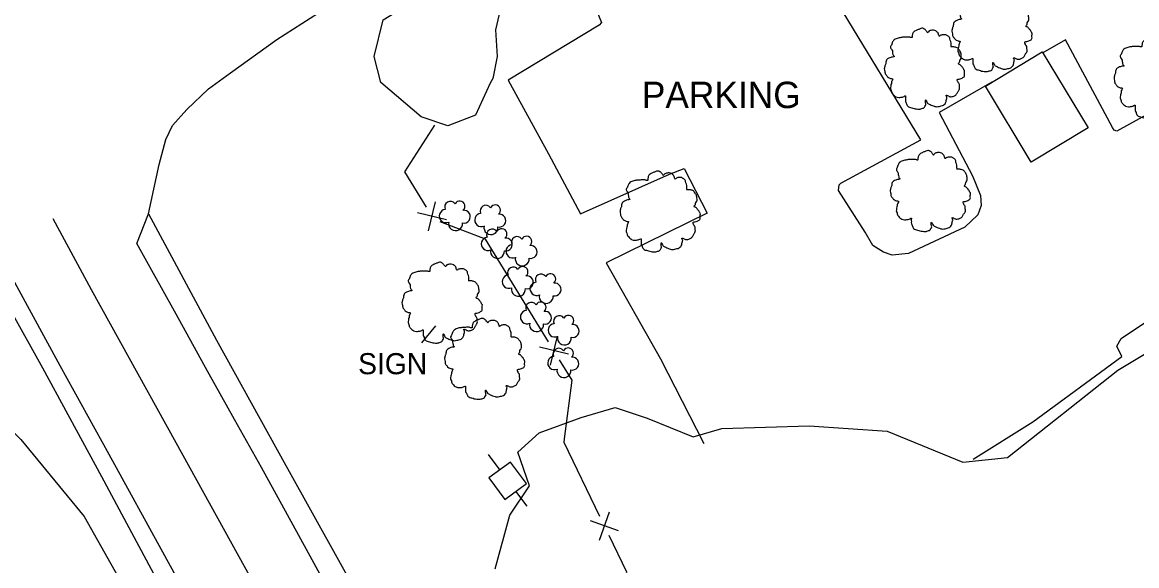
# Model space of a CAD drawing. Extents: x 2160437 to 2172832, y 205694 to 212444.
# Drawn here: x 2171800.7 to 2172011.7, y 206184.5 to 206287.5 of the extents above; entities that cross this region are included whole.
import ezdxf

# ---------------------------------------------------------------- set-up
doc = ezdxf.new("R2010")
doc.units = 0
for name, color, linetype in [('Default', 7, 'Continuous'), ('RD_EX_Bldg', 7, 'Continuous'), ('RD_EX_Bldg_Signs', 7, 'Continuous'), ('RD_EX_BldgApp_txCode', 7, 'Continuous'), ('RD_EX_Fence_Other', 7, 'Continuous'), ('RD_EX_LaneStripe', 7, 'Continuous'), ('RD_EX_Parking_Paved', 7, 'Continuous'), ('RD_EX_Road', 7, 'Continuous'), ('RD_EX_Road_txCode', 7, 'Continuous'), ('RD_EX_UT', 7, 'Continuous'), ('RD_EX_VEG', 7, 'Continuous'), ('RD_EX_VEG_TreeLine', 7, 'Continuous')]:
    doc.layers.add(name, color=color, linetype=linetype)

# ---------------------------------------------------------------- blocks, each defined once
blk = doc.blocks.new('RD_EX_Fnce_Other')
at = {"layer": 'Default'}
for points in [[(-0.0417, -0.0417), (0.0417, 0.0417)], [(-0.0417, 0.0417), (0.0417, -0.0417)]]:
    blk.add_lwpolyline(points, dxfattribs=at)
blk = doc.blocks.new('T2')
at = {"layer": 'RD_EX_VEG'}
for points in [[(0.05, 7.21), (-0.25, 7.24), (-0.57, 7.14), (-0.82, 7.04), (-1.05, 6.96), (-1.27, 6.86), (-1.57, 6.69), (-1.8, 6.49), (-1.92, 6.24), (-1.97, 6.01), (-2.02, 5.74), (-2.02, 5.56), (-2.15, 5.54), (-2.3, 5.56), (-2.55, 5.64), (-2.8, 5.64), (-3.05, 5.64), (-3.4, 5.61), (-3.75, 5.61), (-4.02, 5.56), (-4.35, 5.51), (-4.72, 5.39), (-5.07, 5.26), (-5.37, 5.01), (-5.62, 4.54), (-5.75, 4.19), (-5.9, 3.94), (-5.75, 3.49), (-5.57, 3.14), (-5.55, 2.94), (-5.47, 2.52), (-5.37, 2.29), (-5.25, 2.09), (-5.32, 2.07), (-5.7, 2.02), (-6, 1.92), (-6.42, 1.69), (-6.64, 1.47), (-6.74, 1.14), (-6.77, 0.79), (-6.87, 0.59), (-6.94, 0.32), (-6.97, 0.24), (-7.02, -0.08), (-6.92, -0.53), (-6.89, -0.88), (-6.77, -1.11), (-6.62, -1.28), (-6.44, -1.53), (-6.05, -1.76), (-5.72, -1.86), (-5.52, -1.88), (-5.7, -2.38), (-5.75, -2.73), (-5.87, -3.13), (-5.87, -3.21), (-5.92, -3.68), (-5.77, -4.01), (-5.7, -4.38), (-5.52, -4.61), (-5.25, -4.91), (-4.92, -5.13), (-4.42, -5.26), (-4.02, -5.23), (-3.45, -5.06), (-3.2, -4.98), (-3.22, -5.16), (-3.2, -5.53), (-3.2, -5.96), (-3.05, -6.28), (-2.95, -6.56), (-2.8, -6.81), (-2.47, -7.03), (-2.07, -7.11), (-1.65, -7.26), (-1.2, -7.33), (-0.7, -7.36), (-0.1, -7.21), (0.18, -7.08), (0.28, -6.91), (0.48, -6.53), (0.43, -6.31), (0.45, -5.71), (0.55, -5.88), (0.73, -6.23), (1.23, -6.53), (1.63, -6.71), (2.1, -6.86), (2.4, -6.93), (2.88, -6.86), (3.25, -6.78), (3.63, -6.66), (3.93, -6.38), (4.1, -6.11), (4.15, -5.83), (4.23, -5.46), (4.28, -5.28)], [(4.28, -5.28), (4.2, -5.11), (4.15, -4.86), (4.23, -4.88), (4.4, -4.93), (4.68, -5.06), (4.9, -5.13), (5.23, -5.11), (5.5, -5.01), (5.95, -4.73), (6.22, -4.26), (6.5, -3.86), (6.57, -3.53), (6.52, -3.31), (6.5, -2.81), (6.3, -2.56), (6.25, -2.43), (6.15, -2.03), (6.22, -1.98), (6.5, -1.93), (6.87, -1.81), (7.15, -1.68), (7.37, -1.51), (7.45, -1.28), (7.42, -0.88), (7.47, -0.48), (7.4, -0.33), (7.3, -0.18), (7.22, 0.02), (7.07, 0.17), (6.97, 0.32), (6.87, 0.42), (6.75, 0.57), (6.57, 0.69), (6.42, 0.74), (6.37, 0.89), (6.52, 1.09), (6.57, 1.19), (6.6, 1.42), (6.82, 1.77), (6.87, 2.17), (6.82, 2.59), (6.77, 2.87), (6.62, 3.14), (6.42, 3.39), (6.3, 3.56), (6.12, 3.69), (5.8, 3.81), (5.55, 3.86), (5.2, 3.86), (5, 3.91), (5.03, 3.96), (5.03, 4.11), (5.03, 4.39), (4.95, 4.84), (4.8, 5.34), (4.8, 5.36), (4.7, 5.61), (4.48, 5.81), (4.3, 5.91), (4.1, 6.04), (3.85, 6.06), (3.55, 6.06), (3.28, 6.01), (3.08, 5.91), (2.9, 5.79), (2.83, 5.94), (2.73, 6.24), (2.68, 6.39), (2.53, 6.56), (2.3, 6.76), (1.85, 6.89), (1.23, 6.81), (0.93, 6.61), (0.78, 6.44), (0.73, 6.56), (0.53, 6.76), (0.43, 6.94), (0.25, 7.06), (0.1, 7.16), (0, 7.21)]]:
    blk.add_spline(points, degree=3, dxfattribs=at)
blk = doc.blocks.new('PP')
at = {"layer": 'RD_EX_UT'}
for p, q in [((2.49, 2.51), (-2.51, 2.51)), ((-2.51, 2.51), (-2.51, -2.49)), ((2.49, -2.49), (2.49, 2.51)), ((-5.94, -0.05), (-2.47, -0.05)), ((2.42, -0.05), (6.06, -0.05)), ((-2.51, -2.49), (2.49, -2.49))]:
    blk.add_line(p, q, dxfattribs=at)

msp = doc.modelspace()

# ---------------------------------------------------------------- linework, layer by layer
at = {"layer": 'RD_EX_Bldg'}
msp.add_lwpolyline([(2171993.84, 206281.88), (2172002.51, 206267.47), (2171991.72, 206260.98), (2171983.06, 206275.39)], close=True, dxfattribs=at)
at = {"layer": 'RD_EX_Bldg_Signs'}
msp.add_lwpolyline([(2171878.9, 206229.93), (2171876.26, 206226.72)], dxfattribs=at)
at = {"layer": 'RD_EX_Fence_Other'}
for points in [[(2171877.21, 206252.42), (2171873.1, 206259.12), (2171878.81, 206268)], [(2171900.33, 206226.91), (2171888.41, 206246.36), (2171879.83, 206249.65)], [(2171910.06, 206193.82), (2171903.27, 206207.82), (2171903.35, 206208.53), (2171904.8, 206219.64), (2171902.43, 206223.5)], [(2171917.26, 206161.07), (2171911.5, 206171.27), (2171915.18, 206183.25), (2171911.8, 206190.22)]]:
    msp.add_lwpolyline(points, dxfattribs=at)
at = {"layer": 'RD_EX_LaneStripe'}
msp.add_lwpolyline([(2171915.41, 206052.28), (2171908.6, 206064.84), (2171894.59, 206090.36), (2171876.39, 206123.47), (2171863.18, 206147.44), (2171846.75, 206177.09), (2171829.84, 206207.77), (2171813.79, 206236.79), (2171806.5, 206250.2)], dxfattribs=at)
at = {"layer": 'RD_EX_Parking_Paved'}
for points in [[(2171887.33, 206307.57), (2171892.53, 206306.58), (2171896.05, 206305.57), (2171898.96, 206304.53), (2171901.25, 206303.4), (2171904.57, 206298.7), (2171909.15, 206290.36), (2171910.34, 206287.47), (2171909.9, 206286.91), (2171892.71, 206276.54), (2171900.34, 206262.54), (2171906.36, 206251.17), (2171923.25, 206258.68), (2171926.03, 206259.79), (2171930.39, 206251.32), (2171911.27, 206241.91), (2171921.51, 206223.68), (2171929.73, 206207.64)], [(2171984.28, 206276.13), (2171974.29, 206270.4), (2171980.64, 206258.36), (2171982.14, 206254.64), (2171982.29, 206252.75), (2171981.64, 206250.98), (2171979.17, 206248.66), (2171968.5, 206243.66), (2171965.38, 206243.36), (2171963.75, 206243.89), (2171961.77, 206245.2), (2171960.28, 206247.7), (2171955.23, 206255.61), (2171955.35, 206256.66), (2171955.71, 206257.01), (2171970.86, 206265.23), (2171955.26, 206290.84)], [(2171980.74, 206204.65), (2171992.05, 206211.74), (2172008.92, 206224.14), (2172007.94, 206226.1), (2172008.79, 206227.54), (2172017.45, 206233.35), (2172013.54, 206244.08), (2172019.01, 206247.66), (2172018.01, 206249.68), (2172018.37, 206251.59), (2172019.95, 206252.84), (2172021.51, 206252.84), (2172024.02, 206255.34), (2172026.11, 206255.5), (2172030.82, 206258.52), (2172029.45, 206260.96), (2172027.87, 206261.93), (2172026.71, 206263.93), (2172021.33, 206274.21), (2172007.96, 206266.84), (2172007.44, 206267.03), (2172007.16, 206267.51), (2171998.23, 206284.13), (2171993.96, 206281.68)]]:
    msp.add_lwpolyline(points, dxfattribs=at)
at = {"layer": 'RD_EX_Road'}
for points in [[(2171901.39, 206044.47), (2171876.6, 206089.89), (2171865.46, 206109.54), (2171853.29, 206132.68), (2171840.93, 206155.1), (2171828.92, 206176.69), (2171815.72, 206201.3), (2171804.53, 206221.91), (2171792.02, 206244.4), (2171781.36, 206262.89), (2171770.61, 206282.85), (2171757.79, 206306.7), (2171746.12, 206327.48), (2171731.4, 206354.36), (2171711.51, 206390.94), (2171700.93, 206410.28), (2171689.86, 206429.77), (2171676.21, 206454.51)], [(2171836.45, 206170.39), (2171827.66, 206186.35), (2171817.1, 206205.56), (2171807.83, 206222.34), (2171799.68, 206237.32), (2171792.13, 206251.21), (2171784.29, 206265.31), (2171777.35, 206278.32), (2171770.46, 206291), (2171763.06, 206304.69), (2171755.78, 206317.77), (2171749.27, 206329.78), (2171743.28, 206340.99), (2171736.95, 206352.74), (2171729.52, 206366.17), (2171723.11, 206377.94), (2171717.71, 206387.79), (2171710.52, 206400.59), (2171703.76, 206412.95), (2171697.2, 206424.8), (2171689.07, 206439.41), (2171682.16, 206452.06)], [(2171861.37, 206174.9), (2171855.54, 206185.56), (2171850.89, 206194.12), (2171845.97, 206203.06), (2171840.88, 206212.21), (2171835.73, 206221.38), (2171829.78, 206232.17), (2171824.6, 206241.56), (2171822.35, 206245.55), (2171824.57, 206251.19), (2171826.57, 206260.55), (2171827.86, 206265.24), (2171829.11, 206267.91), (2171831.84, 206270.92), (2171835.93, 206274.88), (2171840.11, 206277.88), (2171848.89, 206284.2), (2171856.74, 206289.3)], [(2171824.57, 206251.19), (2171837.47, 206227.23), (2171850.56, 206203.48), (2171865.85, 206176.01), (2171872.19, 206163.72), (2171883.23, 206144.6), (2171897.67, 206117.65), (2171913.38, 206089.35), (2171928.64, 206061.43)]]:
    msp.add_lwpolyline(points, dxfattribs=at)
at = {"layer": 'RD_EX_VEG'}
for centre, radius, start, end in [((2171881.74, 206252.46), 1.08, 34.9763, 204.756), ((2171883.51, 206252.61), 0.995, 308.7626, 152.0467), ((2171888.45, 206251.72), 1.08, 34.9763, 204.756), ((2171890.22, 206251.87), 0.995, 308.7626, 152.0467), ((2171880.9, 206250.75), 1.26, 96.4518, 294.734), ((2171884.3, 206250.63), 1.22, 256.5667, 98.1046), ((2171887.61, 206250.01), 1.26, 96.4518, 294.734), ((2171891.01, 206249.89), 1.22, 256.5667, 98.1046), ((2171882.71, 206249.31), 1.32, 166.8827, 5.7589), ((2171889.42, 206248.57), 1.32, 166.8827, 5.7589), ((2171889.69, 206247.2), 1.08, 34.9763, 204.756), ((2171891.46, 206247.35), 0.995, 308.7626, 152.0467), ((2171888.85, 206245.49), 1.26, 96.4518, 294.734), ((2171892.25, 206245.37), 1.22, 256.5667, 98.1046), ((2171894.38, 206245.78), 1.08, 34.9763, 204.756), ((2171896.15, 206245.93), 0.995, 308.7626, 152.0467), ((2171890.66, 206244.05), 1.32, 166.8827, 5.7589), ((2171893.54, 206244.07), 1.26, 96.4518, 294.734), ((2171896.94, 206243.95), 1.22, 256.5667, 98.1046), ((2171895.35, 206242.63), 1.32, 166.8827, 5.7589), ((2171893.66, 206240.02), 1.08, 34.9763, 204.756), ((2171895.43, 206240.17), 0.995, 308.7626, 152.0467), ((2171900.69, 206238.82), 0.995, 308.7626, 152.0467), ((2171892.82, 206238.31), 1.26, 96.4518, 294.734), ((2171896.22, 206238.19), 1.22, 256.5667, 98.1046), ((2171898.08, 206236.96), 1.26, 96.4518, 294.734), ((2171898.92, 206238.67), 1.08, 34.9763, 204.756), ((2171901.48, 206236.84), 1.22, 256.5667, 98.1046), ((2171894.63, 206236.87), 1.32, 166.8827, 5.7589), ((2171899.89, 206235.52), 1.32, 166.8827, 5.7589), ((2171897.09, 206233.31), 1.08, 34.9763, 204.756), ((2171898.86, 206233.46), 0.995, 308.7626, 152.0467), ((2171896.25, 206231.6), 1.26, 96.4518, 294.734), ((2171899.65, 206231.48), 1.22, 256.5667, 98.1046), ((2171902.35, 206230.79), 1.08, 34.9763, 204.756), ((2171904.12, 206230.94), 0.995, 308.7626, 152.0467), ((2171898.06, 206230.16), 1.32, 166.8827, 5.7589), ((2171901.51, 206229.08), 1.26, 96.4518, 294.734), ((2171904.91, 206228.96), 1.22, 256.5667, 98.1046), ((2171903.32, 206227.64), 1.32, 166.8827, 5.7589), ((2171902.28, 206224.61), 1.08, 34.9763, 204.756), ((2171904.05, 206224.76), 0.995, 308.7626, 152.0467), ((2171901.44, 206222.9), 1.26, 96.4518, 294.734), ((2171904.84, 206222.78), 1.22, 256.5667, 98.1046), ((2171903.25, 206221.46), 1.32, 166.8827, 5.7589)]:
    msp.add_arc(centre, radius, start, end, dxfattribs=at)
at = {"layer": 'RD_EX_VEG_TreeLine'}
for points in [[(2171889.3, 206275.92), (2171886.47, 206269.85), (2171881.27, 206267.85), (2171876.18, 206269.56), (2171868.58, 206276.05), (2171867.34, 206281.02), (2171869.03, 206287.94), (2171874.4, 206291.25), (2171877.74, 206298.05), (2171883.4, 206300.36), (2171889.64, 206298.13), (2171891.67, 206292.07), (2171890.3, 206286.07), (2171890.63, 206281), (2171889.77, 206276.8)], [(2171800.41, 206208.4), (2171812.38, 206193.79), (2171822.52, 206175.87), (2171820.25, 206163.95), (2171812.17, 206169.17), (2171801.14, 206179.59), (2171789.35, 206199.34), (2171788.93, 206210.22), (2171794.15, 206212.74), (2171797.31, 206211.71), (2171798.85, 206209.94)]]:
    msp.add_lwpolyline(points, close=True, dxfattribs=at)
msp.add_lwpolyline([(2171890.22, 206183.89), (2171892.98, 206194.06), (2171896.71, 206199.62), (2171894.5, 206205.98), (2171898.55, 206209.67), (2171906.5, 206212.54), (2171912.96, 206214.49), (2171918.98, 206212.47), (2171927.74, 206208.9), (2171933.13, 206210.48), (2171949.69, 206211), (2171964.49, 206210), (2171978.79, 206204.13), (2171987.22, 206204.96), (2172008.12, 206221.53), (2172021.21, 206229.35)], dxfattribs=at)

# ---------------------------------------------------------------- block references
at = {"layer": 'RD_EX_Fence_Other'}
for p, xscale, yscale, rotation in [((2171878.26, 206250.72), 48, 48, 121.52972699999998), ((2171901.38, 206225.21), 48, 48, 121.52413500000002), ((2171910.93, 206192.02), 47.99999999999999, 48.00000000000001, 115.841673)]:
    msp.add_blockref('RD_EX_Fnce_Other', p, dxfattribs=dict(at, xscale=xscale, yscale=yscale, rotation=rotation))
at = {"layer": 'RD_EX_UT', "xscale": 1.0199999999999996, "yscale": 1.02, "rotation": 126.43732600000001}
msp.add_blockref('PP', (2171892.62, 206200.58), dxfattribs=at)
at = {"layer": 'RD_EX_VEG', "xscale": 1.0499999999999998, "yscale": 1.0499999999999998}
for p in [(2171984.07, 206285.87), (2171971.29, 206278.75), (2172014.79, 206276.99), (2171972.4, 206255.56), (2171921.24, 206251.69), (2171879.95, 206234.4), (2171887.99, 206223.75)]:
    msp.add_blockref('T2', p, dxfattribs=at)

# ---------------------------------------------------------------- texts
at = {"layer": 'RD_EX_BldgApp_txCode'}
msp.add_text('SIGN', height=4, dxfattribs=at).set_placement((2171864.27, 206220.77))
at = {"layer": 'RD_EX_Road_txCode'}
msp.add_text('PARKING', height=5, dxfattribs=at).set_placement((2171918, 206271.22))

doc.saveas('drawing.dxf')
